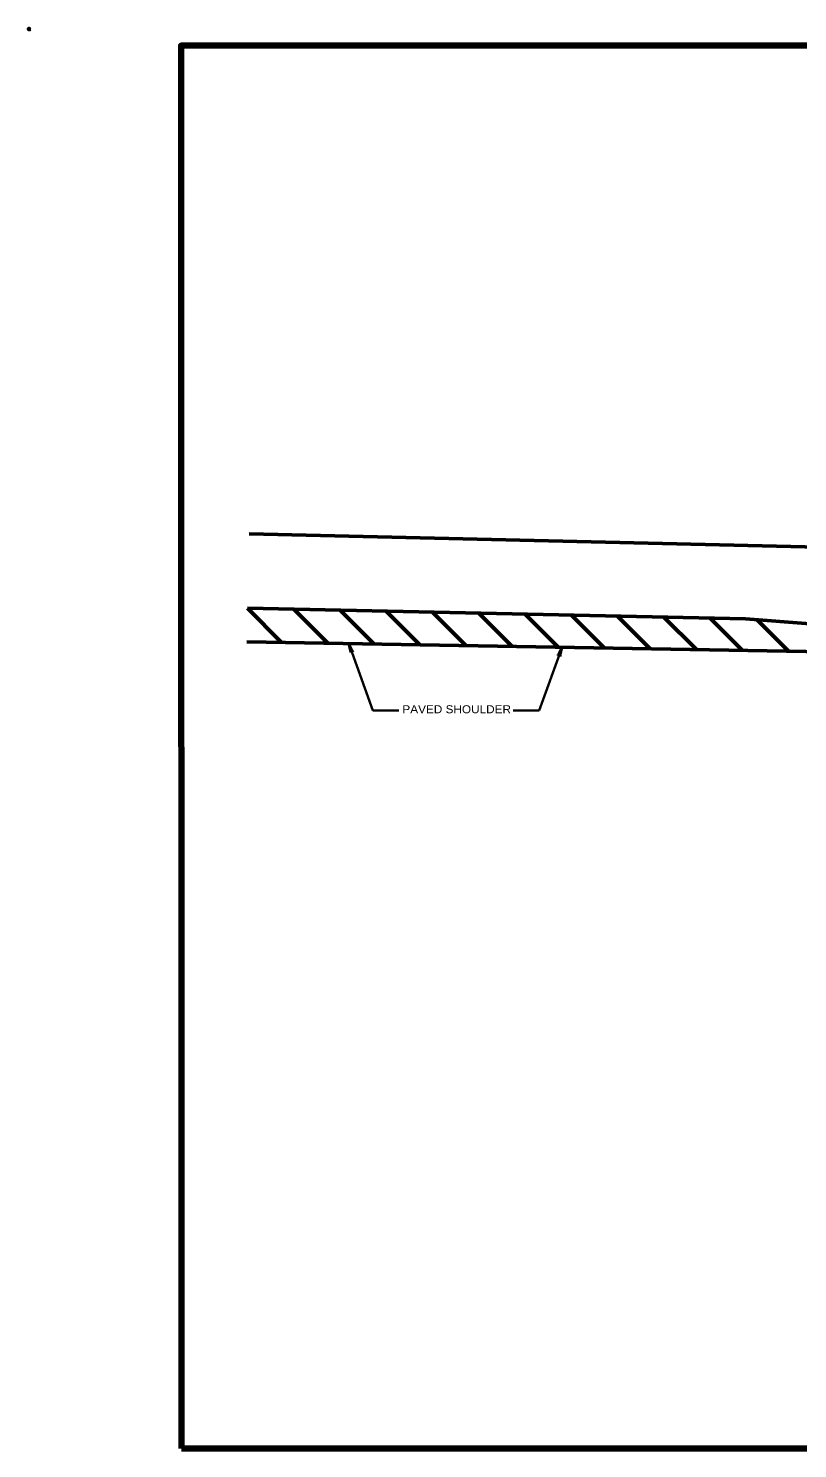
# Model space of a CAD drawing. Extents: x -371 to 484, y -338 to 206.
# Drawn here: x -371 to -83, y -326 to 206 of the extents above; entities that cross this region are included whole.
import ezdxf

# ---------------------------------------------------------------- set-up
doc = ezdxf.new("R2010")
doc.units = 0
doc.header["$PDMODE"] = 32
doc.header["$PDSIZE"] = 0.5
doc.layers.add('1', color=7, linetype='Continuous', lineweight=53)

msp = doc.modelspace()

# ---------------------------------------------------------------- linework, layer by layer
at = {"layer": '1'}
for p, q in [((-288.756, 16.515), (43.484, 8.747)), ((-276.514, -24.219), (-289.325, -11.408)), ((-259.241, -24.521), (-271.98, -11.782)), ((-241.967, -24.824), (-254.636, -12.155)), ((-224.694, -25.127), (-237.292, -12.529)), ((-207.421, -25.43), (-219.947, -12.903)), ((-190.147, -25.732), (-202.603, -13.277)), ((-172.874, -26.035), (-185.259, -13.65)), ((-155.601, -26.338), (-167.914, -14.024)), ((-138.327, -26.641), (-150.57, -14.398)), ((-121.054, -26.943), (-133.226, -14.772)), ((-103.781, -27.246), (-115.882, -15.145)), ((-86.507, -27.549), (-98.291, -15.765))]:
    msp.add_line(p, q, dxfattribs=at)
at = {"layer": '1', "lineweight": 35}
for p, q in [((-171.404, -26.061), (-179.969, -49.724)), ((-179.969, -49.724), (-189.706, -49.724))]:
    msp.add_line(p, q, dxfattribs=at)
at = {"layer": '1', "lineweight": 158}
msp.add_line((477.495, -326.494), (-314.105, -326.494), dxfattribs=at)
msp.add_lwpolyline([(477.495, 199.606), (-314.205, 199.506), (-314.105, -326.494)], dxfattribs=at)
at = {"layer": '1'}
for points in [[(-289.357, -11.407), (-102.62, -15.431), (458.068, -58.713)], [(460.106, -65.505), (-7.77, -28.929), (-289.578, -23.989)]]:
    msp.add_lwpolyline(points, dxfattribs=at)
at = {"layer": '1', "lineweight": 35}
msp.add_lwpolyline([(-251.356, -24.66), (-242.284, -49.724), (-232.547, -49.724)], dxfattribs=at)
at = {"layer": '1', "lineweight": 40}
for centre, major_axis, ratio, start_param, end_param in [((-251.137, -26.01), (-0.519, 2.054), 0.07063, 3.1407148, 5.41811), ((-251.137, -26.01), (-0.519, 2.054), 0.07063, 3.1407148, 5.41811), ((-250.598, -25.778), (-0.905, 1.951), 0.122415, 0.8963533, 3.1415927), ((-250.598, -25.778), (-0.905, 1.951), 0.122415, 0.8963533, 3.1415927), ((-172.1, -27.239), (0.916, 1.91), 0.07063, 3.1407148, 5.41811), ((-171.538, -27.405), (0.553, 2.079), 0.122415, 0.8963533, 3.1415927)]:
    msp.add_ellipse(centre, major_axis=major_axis, ratio=ratio, start_param=start_param, end_param=end_param, dxfattribs=at)
at = {"layer": '1'}
msp.add_point((-371.205, 205.706), dxfattribs=at)

# ---------------------------------------------------------------- texts
at = {"layer": '1', "width": 1.1}
msp.add_text('PAVED SHOULDER', height=3, dxfattribs=at).set_placement((-231.249, -50.807))

doc.saveas('drawing.dxf')
